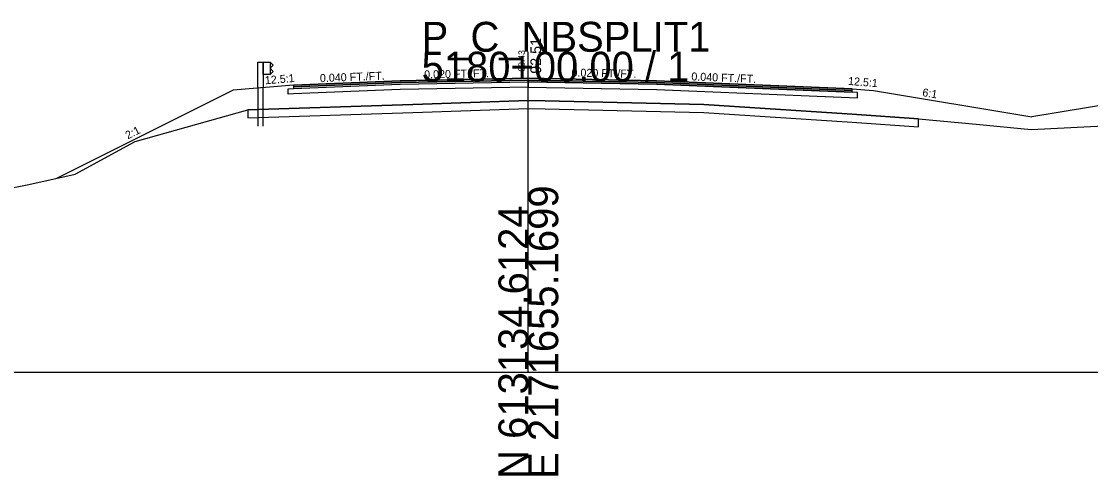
# Model space of a CAD drawing. Extents: x -26 to 1303, y -3010 to 12038.
# Drawn here: x 102.5 to 202.7, y 3490.3 to 3532.8 of the extents above; entities that cross this region are included whole.
import ezdxf

# ---------------------------------------------------------------- set-up
doc = ezdxf.new("R2010")
doc.units = 0
for name, color, linetype in [('RD_GPK_XS_Cell', 7, 'Continuous'), ('RD_PD_Final_TrvlWay', 7, 'Continuous'), ('RD_XS_Base', 7, 'Continuous'), ('RD_XS_ExGround', 7, 'Continuous'), ('RD_XS_ExPaveRet', 7, 'Continuous'), ('RD_XS_GR', 7, 'Continuous'), ('RD_XS_Greenside', 7, 'Continuous'), ('RD_XS_Pave', 7, 'Continuous'), ('RD_XS_PaveOvlay_CP', 7, 'Continuous'), ('RD_XS_TieSlope', 7, 'Continuous'), ('RD_XS_TX_Elev_EX', 7, 'Continuous'), ('RD_XS_TX_Elev_PR', 7, 'Continuous'), ('RD_XS_TX_ShdSlope', 7, 'Continuous'), ('RD_XS_TX_Slope', 7, 'Continuous')]:
    doc.layers.add(name, color=color, linetype=linetype)

msp = doc.modelspace()

# ---------------------------------------------------------------- linework, layer by layer
at = {"layer": 'RD_GPK_XS_Cell'}
for p, q in [((150, 3500), (150, 3530)), ((0, 3500), (150, 3500)), ((150, 3500), (300, 3500))]:
    msp.add_line(p, q, dxfattribs=at)
at = {"layer": 'RD_PD_Final_TrvlWay'}
for p, q in [((125.17, 3526.64), (124.67, 3526.6)), ((124.67, 3526.6), (124.67, 3523.03)), ((125.17, 3523.03), (125.17, 3526.64))]:
    msp.add_line(p, q, dxfattribs=at)
at = {"layer": 'RD_XS_Base'}
for p, q in [((128, 3526.55), (138, 3526.95)), ((138, 3526.95), (150, 3527.19)), ((138, 3526.95), (138, 3526.95)), ((150, 3527.19), (150, 3527.35)), ((150, 3527.35), (150, 3526.69)), ((150, 3527.19), (150, 3526.69)), ((162, 3526.95), (150, 3527.19)), ((150, 3527.19), (150, 3527.19)), ((180.33, 3526.21), (162, 3526.95)), ((164, 3526.87), (164, 3526.87)), ((127.5, 3526.53), (128, 3526.55)), ((127.5, 3526.03), (127.5, 3526.53)), ((127.5, 3526.53), (127.5, 3526.53)), ((128, 3526.05), (127.5, 3526.03)), ((127.5, 3526.03), (127.5, 3526.03)), ((127.5, 3526.03), (127.5, 3526.03)), ((128, 3526.55), (128, 3526.55)), ((138, 3526.45), (128, 3526.05)), ((128, 3526.05), (128, 3526.05)), ((150, 3526.69), (138, 3526.45)), ((138, 3526.45), (138, 3526.45)), ((150, 3526.69), (150, 3526.69)), ((150, 3526.69), (150, 3526.69)), ((150, 3526.69), (162, 3526.45)), ((162, 3526.45), (180.83, 3525.69)), ((164, 3526.37), (164, 3526.37)), ((180.83, 3526.19), (180.33, 3526.21)), ((180.33, 3526.21), (180.33, 3526.21)), ((180.83, 3525.69), (180.83, 3526.19)), ((180.83, 3526.19), (180.83, 3526.19)), ((180.83, 3525.69), (180.83, 3525.69)), ((180.83, 3525.69), (180.83, 3525.69))]:
    msp.add_line(p, q, dxfattribs=at)
at = {"layer": 'RD_XS_ExGround'}
msp.add_lwpolyline([(98.13, 3516.56), (103.21, 3517.57), (107.55, 3518.52), (113.12, 3521.57), (113.13, 3521.58), (113.15, 3521.59), (113.18, 3521.6), (123.73, 3524.56), (139.17, 3525.07), (149.98, 3525.43), (151.57, 3525.39), (166.45, 3525.05), (180.33, 3524.16), (186.56, 3523.72), (191.94, 3523.21), (197.11, 3522.72), (207.6, 3523.25)], dxfattribs=at)
at = {"layer": 'RD_XS_ExPaveRet'}
for points in [[(180.33, 3524.16), (166.45, 3525.05), (166.45, 3525.05), (166.45, 3525.05), (151.57, 3525.39), (151.57, 3525.39), (149.98, 3525.43), (139.17, 3525.07), (139.17, 3525.07), (123.73, 3524.56), (123.73, 3523.81), (123.73, 3523.81), (139.17, 3524.32), (139.17, 3524.32), (149.98, 3524.68), (151.57, 3524.64), (151.57, 3524.64), (166.45, 3524.3), (166.45, 3524.3), (166.45, 3524.3), (180.33, 3523.41), (180.33, 3523.41), (186.56, 3522.97), (186.56, 3522.97), (186.56, 3523.72), (180.33, 3524.16), (180.33, 3524.16)], [(166.45, 3525.05), (151.57, 3525.39), (149.98, 3525.43), (139.17, 3525.07), (123.73, 3524.56), (123.73, 3523.81), (139.17, 3524.32), (149.98, 3524.68), (151.57, 3524.64), (166.45, 3524.3), (180.33, 3523.41), (186.56, 3522.97), (186.56, 3523.72)], [(186.56, 3523.72), (180.33, 3524.16), (166.45, 3525.05)]]:
    msp.add_lwpolyline(points, dxfattribs=at)
at = {"layer": 'RD_XS_GR'}
for points in [[(125.17, 3529.03), (125.17, 3526.64), (124.67, 3526.6), (124.67, 3529.03), (124.92, 3529.03), (125.17, 3529.03)], [(125.83, 3529.03), (125.83, 3527.87), (125.17, 3527.87), (125.17, 3529.03), (125.83, 3529.03)], [(126.1, 3528.74), (125.83, 3529.03), (125.83, 3527.87), (125.83, 3527.87), (125.83, 3527.87), (126.1, 3528.16), (126.1, 3528.16), (125.83, 3528.45), (125.83, 3528.45), (126.1, 3528.74), (126.1, 3528.74)]]:
    msp.add_lwpolyline(points, dxfattribs=at)
at = {"layer": 'RD_XS_Greenside'}
for p, q in [((122.35, 3526.41), (105.8, 3518.13)), ((182.33, 3526.37), (197.17, 3523.9)), ((210.24, 3526.08), (197.17, 3523.9))]:
    msp.add_line(p, q, dxfattribs=at)
at = {"layer": 'RD_XS_Pave'}
for p, q in [((138, 3527.27), (128, 3526.87)), ((138, 3527.11), (128, 3526.71)), ((128, 3526.71), (138, 3527.11)), ((128, 3526.55), (138, 3526.95)), ((128, 3526.87), (128, 3526.87)), ((128, 3526.87), (128, 3526.71)), ((150, 3527.51), (138, 3527.27)), ((150, 3527.35), (138, 3527.11)), ((138, 3527.11), (150, 3527.35)), ((138, 3527.27), (138, 3527.27)), ((138, 3526.95), (150, 3527.19)), ((138, 3527.11), (138, 3527.11)), ((138, 3527.11), (138, 3527.11)), ((138, 3526.95), (138, 3526.95)), ((162, 3527.27), (150, 3527.51)), ((150, 3527.19), (150, 3527.35)), ((150, 3527.35), (162, 3527.11)), ((162, 3527.11), (150, 3527.35)), ((150, 3527.35), (150, 3527.19)), ((150, 3527.19), (150, 3527.19)), ((150, 3527.19), (150, 3527.19)), ((150, 3527.19), (162, 3526.95)), ((180.33, 3526.53), (162, 3527.27)), ((162, 3527.11), (180.33, 3526.37)), ((180.33, 3526.37), (162, 3527.11)), ((162, 3526.95), (180.33, 3526.21)), ((164, 3527.19), (164, 3527.19)), ((164, 3527.03), (164, 3527.03)), ((164, 3527.03), (164, 3527.03)), ((164, 3526.87), (164, 3526.87)), ((128, 3526.71), (128, 3526.71)), ((128, 3526.71), (128, 3526.55)), ((128, 3526.71), (128, 3526.71)), ((128, 3526.71), (128, 3526.71)), ((128, 3526.55), (128, 3526.55)), ((128, 3526.55), (128, 3526.55)), ((180.33, 3526.37), (180.33, 3526.53)), ((180.33, 3526.53), (180.33, 3526.53)), ((180.33, 3526.37), (180.33, 3526.37)), ((180.33, 3526.37), (180.33, 3526.37)), ((180.33, 3526.21), (180.33, 3526.37)), ((180.33, 3526.37), (180.33, 3526.37)), ((180.33, 3526.21), (180.33, 3526.21)), ((180.33, 3526.21), (180.33, 3526.21))]:
    msp.add_line(p, q, dxfattribs=at)
at = {"layer": 'RD_XS_PaveOvlay_CP'}
for p, q in [((128, 3526.87), (138, 3527.27)), ((138, 3527.27), (150, 3527.51)), ((150, 3527.51), (162, 3527.27)), ((162, 3527.27), (180.33, 3526.53))]:
    msp.add_line(p, q, dxfattribs=at)
at = {"layer": 'RD_XS_TieSlope'}
for p, q in [((128, 3526.87), (122.35, 3526.41)), ((180.33, 3526.53), (182.33, 3526.37))]:
    msp.add_line(p, q, dxfattribs=at)

# ---------------------------------------------------------------- texts
at = {"layer": 'RD_GPK_XS_Cell'}
for s, p in [('P_C_NBSPLIT1', (140, 3530)), ('5180+00.00 / 1', (140, 3527.2))]:
    msp.add_text(s, height=2.8, dxfattribs=at).set_placement(p)
for s, p in [('E 2171655.1699', (152.8, 3490)), ('N 613134.6124', (150, 3490))]:
    msp.add_text(s, height=2.8, rotation=90, dxfattribs=at).set_placement(p)
at = {"layer": 'RD_XS_TX_Elev_EX'}
msp.add_text('90.43', height=0.6, rotation=90, dxfattribs=at).set_placement((149.67, 3528.14))
at = {"layer": 'RD_XS_TX_Elev_PR'}
msp.add_text('92.51', height=1, rotation=90, dxfattribs=at).set_placement((151.2, 3527.94))
at = {"layer": 'RD_XS_TX_ShdSlope'}
for rotation, p in [(4.5739, (125.35, 3526.95)), (355.4261, (179.93, 3526.9))]:
    msp.add_text('12.5:1', height=0.75, rotation=rotation, dxfattribs=at).set_placement(p)
at = {"layer": 'RD_XS_TX_Slope'}
for s, rotation, p in [('0.040 FT./FT.', 2.2906, (130.49, 3527.15)), ('0.020 FT./FT.', 1.1458, (140.25, 3527.5)), ('0.020 FT./FT.', 358.8542, (154.04, 3527.68)), ('0.040 FT./FT.', 357.7094, (165.26, 3527.32)), ('6:1', 350.5377, (186.87, 3525.85)), ('2:1', 26.5651, (112.48, 3521.78))]:
    msp.add_text(s, height=0.75, rotation=rotation, dxfattribs=at).set_placement(p)

doc.saveas('drawing.dxf')
